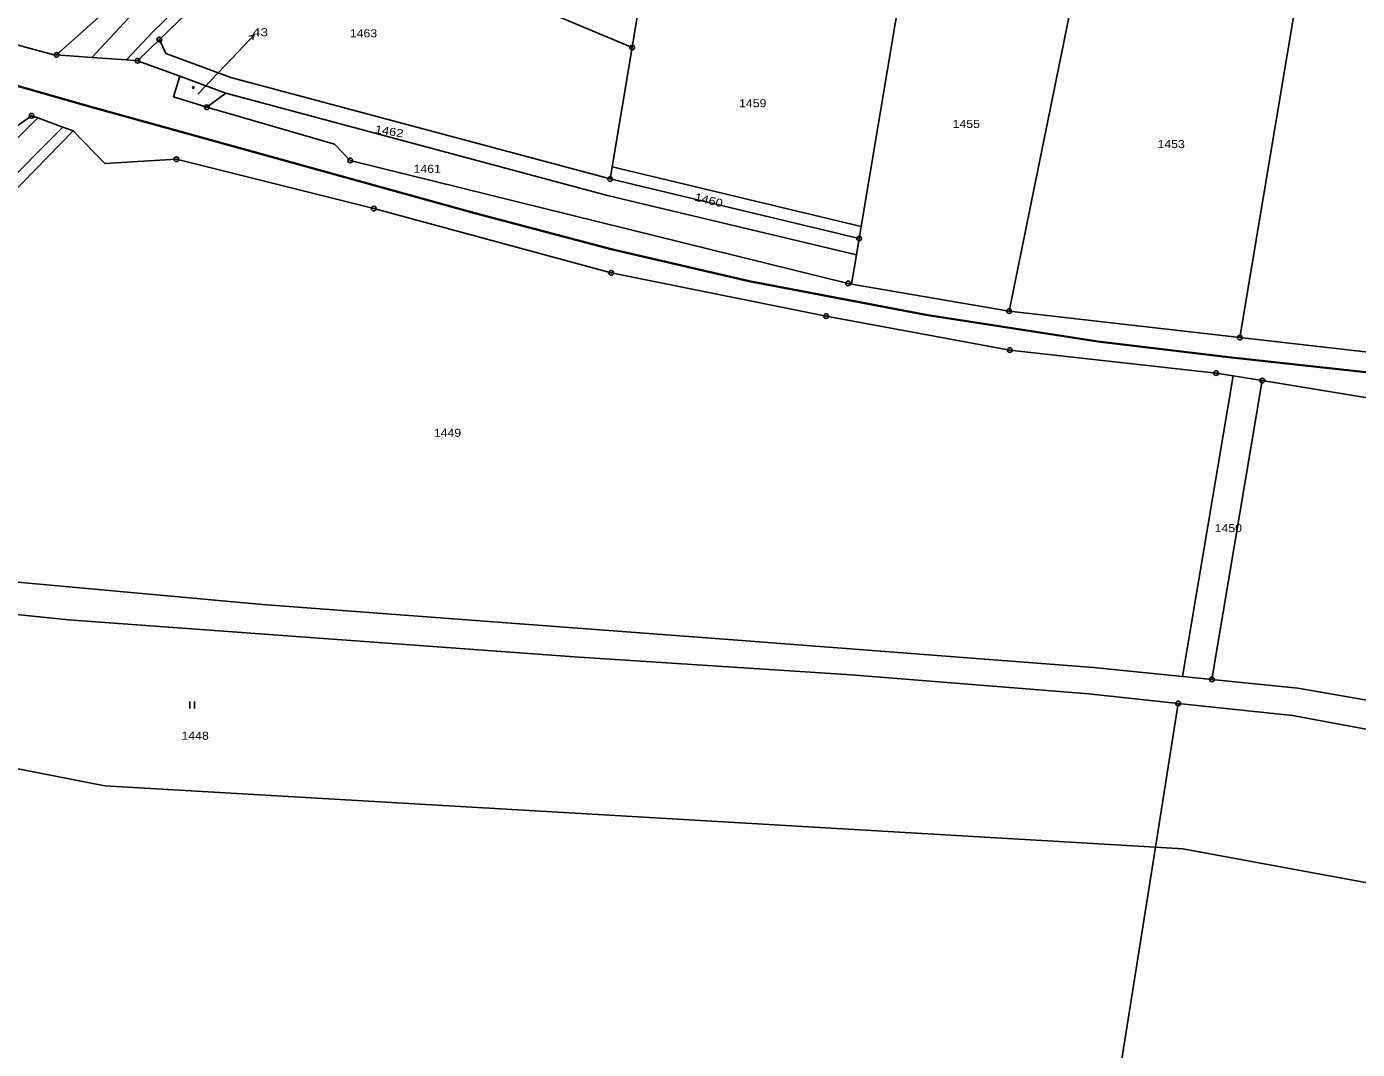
# Model space of a CAD drawing. Extents: x -872229 to -869198, y -1075981 to -1074329.
# Drawn here: x -871207 to -870924.3, y -1075586.7 to -1075369.5 of the extents above; entities that cross this region are included whole.
import ezdxf
from ezdxf.enums import TextEntityAlignment as Align

# ---------------------------------------------------------------- set-up
doc = ezdxf.new("R2010")
doc.units = 0
doc.header["$LTSCALE"] = 0.68
for name, color, linetype, lineweight in [('1', 7, 'Continuous', 25), ('3', 7, 'Continuous', 25), ('4', 7, 'Continuous', 13), ('5', 7, 'Continuous', 25), ('6', 7, 'Continuous', 25), ('7', 7, 'Continuous', 13), ('8', 7, 'Continuous', 25)]:
    doc.layers.add(name, color=color, linetype=linetype, lineweight=lineweight)
doc.layers.add('2', color=7, linetype='Continuous')

msp = doc.modelspace()

# ---------------------------------------------------------------- linework, layer by layer
at = {"layer": '1'}
for p, q in [((-871149.52, -1075343.97), (-871178.79, -1075372.22)), ((-871078.37, -1075373.89), (-871149.52, -1075343.97)), ((-871183.42, -1075376.69), (-871174.48, -1075379.98))]:
    msp.add_line(p, q, dxfattribs=at)
for points in [[(-871146.74, -1075326.85), (-871149.26, -1075329.47), (-871152.59, -1075332.45), (-871180.67, -1075357.59), (-871200.62, -1075375.46)], [(-870928.54, -1075345.19), (-870929.33, -1075345.1), (-870934.07, -1075344.52), (-870949.31, -1075435.5)], [(-871074.84, -1075352.78), (-871077.5, -1075368.64), (-871078.37, -1075373.89), (-871082.62, -1075399.25), (-871029.72, -1075411.9)], [(-870984.86, -1075363.6), (-871020.66, -1075357.83), (-871029.72, -1075411.9), (-871030.15, -1075414.48), (-871030.73, -1075417.93), (-871031.77, -1075424.14), (-870998.3, -1075429.88)], [(-871243.8, -1075363.33), (-871207.98, -1075373.63), (-871201.2, -1075375.48), (-871200.62, -1075375.46)], [(-870984.86, -1075363.6), (-870998.3, -1075429.88), (-870949.31, -1075435.5)], [(-871083.05, -1075401.82), (-871163.59, -1075380.25), (-871177.43, -1075375.17), (-871178.79, -1075372.22), (-871183.42, -1075376.69)], [(-871200.62, -1075375.46), (-871193.17, -1075376.03), (-871185.81, -1075376.53), (-871183.42, -1075376.69)], [(-871030.73, -1075417.93), (-871083.63, -1075405.29), (-871164.66, -1075383.59)], [(-871168.71, -1075386.58), (-871141.62, -1075394.43), (-871138.24, -1075397.87), (-871032.51, -1075424.01), (-871031.77, -1075424.14)], [(-871197.08, -1075391.62), (-871199.28, -1075390.81), (-871204.62, -1075388.86), (-871205.94, -1075388.38), (-871212.24, -1075392.84)], [(-871197.08, -1075391.62), (-871246.11, -1075441.8), (-871278.54, -1075475.47)], [(-870950.68, -1075443.64), (-870954.33, -1075443.04), (-870998.17, -1075438.16), (-871037.17, -1075430.94), (-871082.81, -1075421.77), (-871133.25, -1075408.1), (-871175.19, -1075397.63), (-871190.41, -1075398.53), (-871197.08, -1075391.62)], [(-871082.62, -1075399.25), (-871083.05, -1075401.82), (-871030.15, -1075414.48)], [(-870949.31, -1075435.5), (-870912.76, -1075439.69), (-870824.05, -1075448.17), (-870816.69, -1075448.69), (-870813.04, -1075448.95), (-870783.54, -1075451.03), (-870689.55, -1075462.28), (-870596.02, -1075472.9), (-870575.95, -1075474.7)], [(-871278.54, -1075475.47), (-871235.98, -1075483.88), (-871218.31, -1075486.6), (-871156.9, -1075492.22), (-871055.97, -1075499.77), (-870980.4, -1075505.56), (-870961.43, -1075507.47), (-870950.68, -1075443.64)], [(-870961.43, -1075507.47), (-870955.2, -1075508.1), (-870944.51, -1075444.65), (-870950.68, -1075443.64)], [(-870817.87, -1075462.75), (-870872.87, -1075452.61), (-870914.84, -1075449.51), (-870944.51, -1075444.65)], [(-870962.39, -1075513.2), (-870981.34, -1075511.21), (-871031.87, -1075507.16), (-871090.68, -1075503.32), (-871198.07, -1075495.44), (-871222.24, -1075493), (-871248.51, -1075487.96), (-871283.35, -1075480.46)], [(-870967.23, -1075543.73), (-871082, -1075537.03), (-871190.36, -1075530.7), (-871309.29, -1075507.4)], [(-870955.2, -1075508.1), (-870936.99, -1075509.94), (-870905.68, -1075515.44), (-870845.51, -1075527.2), (-870825.33, -1075530.87)], [(-870769.48, -1075546.88), (-870771.86, -1075546.41), (-870820.28, -1075537.54), (-870823.66, -1075536.9), (-870849.48, -1075531.79), (-870906.42, -1075521.68), (-870938.07, -1075515.76), (-870962.39, -1075513.2), (-870967.23, -1075543.73)], [(-870967.23, -1075543.73), (-870990.41, -1075689.92), (-871013.78, -1075837.33)], [(-870775.56, -1075578.36), (-870961.39, -1075544.07), (-870967.23, -1075543.73)]]:
    msp.add_lwpolyline(points, dxfattribs=at)
msp.add_lwpolyline([(-871174.48, -1075379.98), (-871175.76, -1075384.38), (-871168.71, -1075386.58), (-871164.66, -1075383.59)], close=True, dxfattribs=at)
at = {"layer": '3'}
for p, q in [((-871172.351, -1075514.29), (-871172.351, -1075512.79)), ((-871171.35, -1075514.29), (-871171.35, -1075512.79))]:
    msp.add_line(p, q, dxfattribs=at)
at = {"layer": '4'}
for p, q in [((-871180.16, -1075370.54), (-871118.25, -1075310.04)), ((-871185.81, -1075376.53), (-871180.16, -1075370.54)), ((-871199.28, -1075390.81), (-871239.07, -1075430.66))]:
    msp.add_line(p, q, dxfattribs=at)
for points in [[(-871144.78, -1075328.38), (-871161.44, -1075344.27), (-871180.53, -1075362.44), (-871193.17, -1075376.03)], [(-871326.72, -1075514.76), (-871291.4, -1075477.73), (-871251.44, -1075435.93), (-871204.62, -1075388.86)]]:
    msp.add_lwpolyline(points, dxfattribs=at)
at = {"layer": '5'}
msp.add_circle((-871171.5668, -1075382.3992), 0.175, dxfattribs=at)
at = {"layer": '6', "lineweight": 35}
for p, q in [((-871192.83, -1075386.61), (-871111.78, -1075409.09)), ((-871053.48, -1075423.53), (-871015.95, -1075430.68))]:
    msp.add_line(p, q, dxfattribs=at)
for points in [[(-871283.38, -1075360.82), (-871232.19, -1075375.42), (-871192.83, -1075386.61)], [(-871111.78, -1075409.09), (-871082.8, -1075416.75), (-871053.48, -1075423.53)], [(-871015.95, -1075430.68), (-870979.48, -1075436.37), (-870951.66, -1075439.69), (-870910.94, -1075444.16)]]:
    msp.add_lwpolyline(points, dxfattribs=at)
at = {"layer": '7'}
msp.add_line((-871158.683, -1075371.165), (-871159.733, -1075371.556), dxfattribs=at)
msp.add_lwpolyline([(-871170.66, -1075383.82), (-871160.73, -1075373.36), (-871158.683, -1075371.165), (-871159, -1075372.239)], dxfattribs=at)
at = {"layer": '8'}
for centre, radius in [((-871178.79, -1075372.2199), 0.5), ((-871178.79, -1075372.2199), 0.0303), ((-871078.37, -1075373.8899), 0.5), ((-871078.37, -1075373.8899), 0.0303), ((-871200.62, -1075375.4599), 0.5), ((-871200.62, -1075375.4599), 0.0303), ((-871183.42, -1075376.6899), 0.5), ((-871183.42, -1075376.6899), 0.0303), ((-871205.94, -1075388.3799), 0.5), ((-871168.71, -1075386.5799), 0.5), ((-871168.71, -1075386.5799), 0.0303), ((-871205.94, -1075388.3799), 0.0303), ((-871175.19, -1075397.6299), 0.5), ((-871175.19, -1075397.6299), 0.0303), ((-871138.24, -1075397.8699), 0.5), ((-871138.24, -1075397.8699), 0.0303), ((-871083.05, -1075401.8199), 0.5), ((-871083.05, -1075401.8199), 0.0303), ((-871133.25, -1075408.0999), 0.5), ((-871133.25, -1075408.0999), 0.0303), ((-871030.15, -1075414.4799), 0.5), ((-871030.15, -1075414.4799), 0.0303), ((-871082.81, -1075421.7699), 0.5), ((-871082.81, -1075421.7699), 0.0303), ((-871032.51, -1075424.0099), 0.5), ((-871032.51, -1075424.0099), 0.0303), ((-871037.17, -1075430.9399), 0.5), ((-870998.3, -1075429.8799), 0.5), ((-870998.3, -1075429.8799), 0.0303), ((-871037.17, -1075430.9399), 0.0303), ((-870949.31, -1075435.4999), 0.5), ((-870949.31, -1075435.4999), 0.0303), ((-870998.17, -1075438.1599), 0.5), ((-870998.17, -1075438.1599), 0.0303), ((-870954.33, -1075443.0399), 0.5), ((-870954.33, -1075443.0399), 0.0303), ((-870944.51, -1075444.6499), 0.5), ((-870944.51, -1075444.6499), 0.0303), ((-870955.2, -1075508.0999), 0.5), ((-870955.2, -1075508.0999), 0.0303), ((-870962.39, -1075513.1999), 0.5), ((-870962.39, -1075513.1999), 0.0303)]:
    msp.add_circle(centre, radius, dxfattribs=at)

# ---------------------------------------------------------------- texts
at = {"layer": '2', "width": 1.3}
msp.add_text('43', height=1.7, dxfattribs=at).set_placement((-871157.34, -1075371.49), align=Align.CENTER)
at = {"layer": '2', "width": 1.15}
for s, p in [('1463', (-871138.35, -1075371.73)), ('1459', (-871055.67, -1075386.58)), ('1455', (-871010.3, -1075390.98)), ('1453', (-870966.78, -1075395.26)), ('1461', (-871124.82, -1075400.51)), ('1449', (-871120.51, -1075456.58)), ('1450', (-870954.64, -1075476.83)), ('1448', (-871174.11, -1075520.93))]:
    msp.add_text(s, height=1.7, dxfattribs=at).set_placement(p)
at = {"layer": '2', "width": 1.2}
for s, rotation, p in [('1462', 351, (-871133.092, -1075392.049)), ('1460', 346, (-871065.245, -1075406.384))]:
    msp.add_text(s, height=1.7, rotation=rotation, dxfattribs=at).set_placement(p)

doc.saveas('drawing.dxf')
